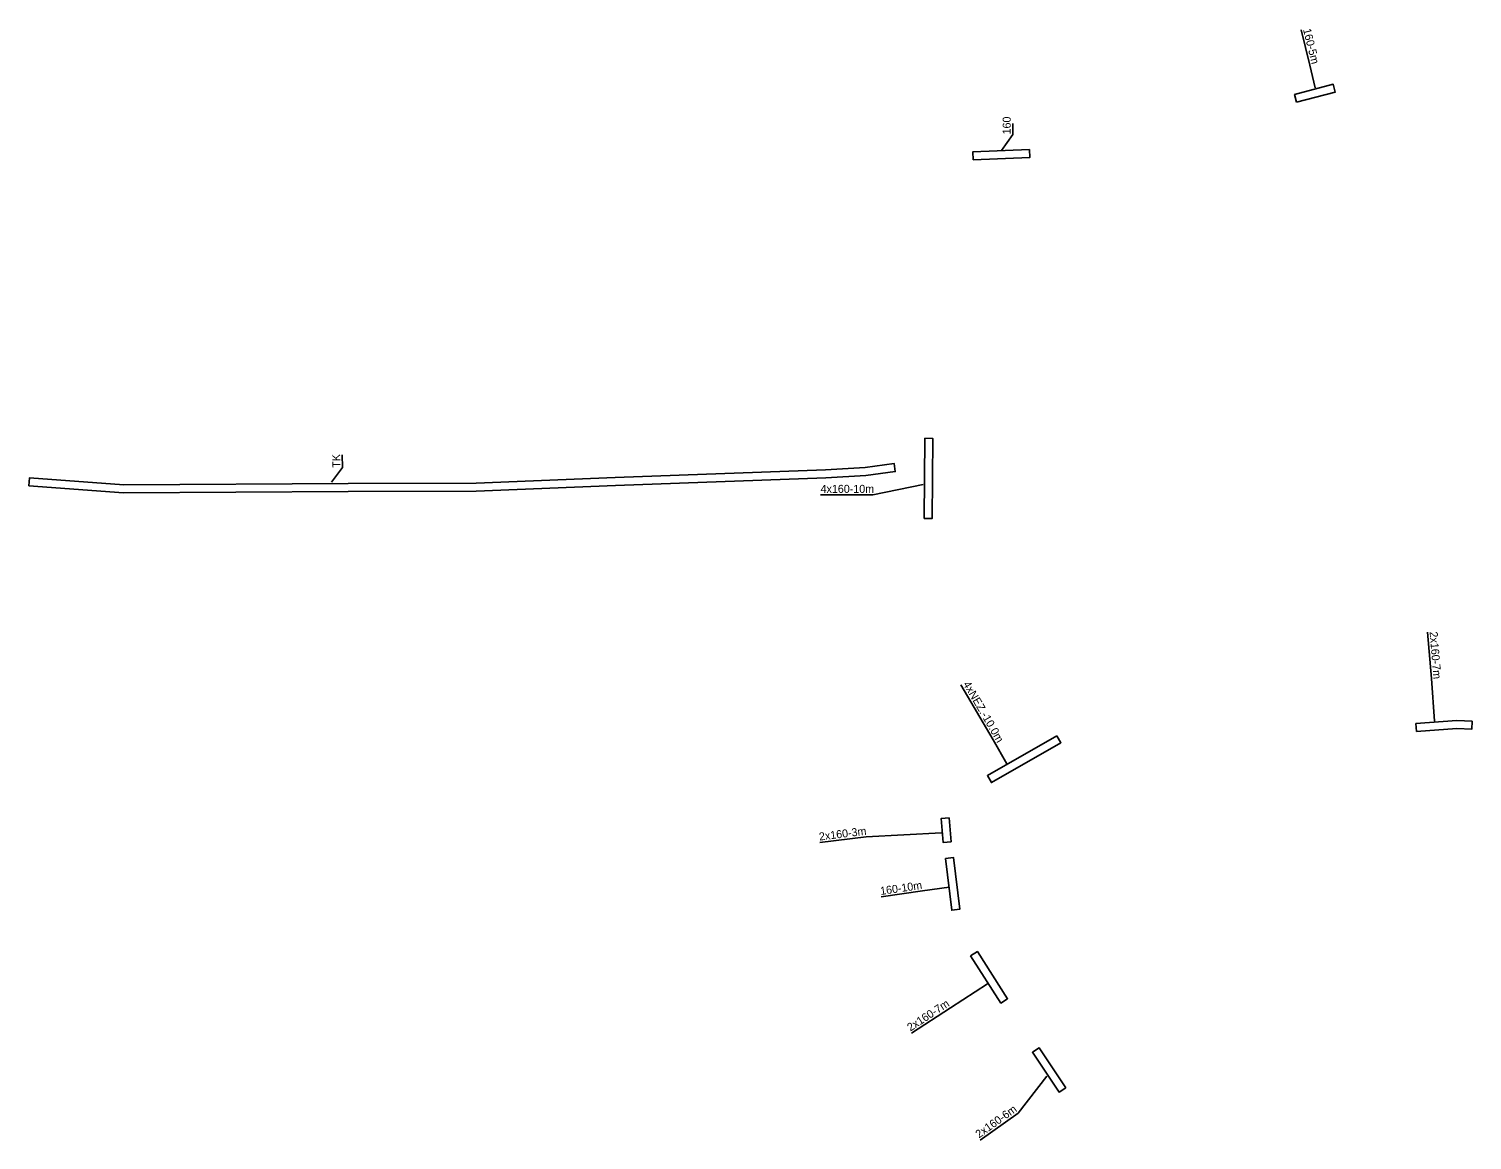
# Model space of a CAD drawing. Extents: x -732155 to -731960, y -1048709 to -1047981.
# Drawn here: x -732154.9 to -731974.6, y -1048120 to -1047981.1 of the extents above; entities that cross this region are included whole.
import ezdxf

# ---------------------------------------------------------------- set-up
doc = ezdxf.new("R2010")
doc.units = 0
doc.layers.add('Chránička', color=7, linetype='Continuous')
doc.layers.add('ST_CHRANICKA_POPIS', color=7, linetype='Continuous')

msp = doc.modelspace()

# ---------------------------------------------------------------- linework, layer by layer
at = {"layer": 'Chránička'}
for points in [[(-731996.497, -1047990.229), (-731996.749, -1047989.261), (-731991.91, -1047988.002), (-731991.658, -1047988.97), (-731996.497, -1047990.229)], [(-732036.908, -1047997.458), (-732036.952, -1047996.458), (-732029.874, -1047996.152), (-732029.83, -1047997.152), (-732036.908, -1047997.458)], [(-732042.939, -1048032.249), (-732041.939, -1048032.257), (-732042.017, -1048042.257), (-732043.017, -1048042.249), (-732042.939, -1048032.249)], [(-732154.881, -1048038.194), (-732154.809, -1048037.196), (-732143.028, -1048038.053), (-732114.98, -1048037.884), (-732099.001, -1048037.839), (-732081.607, -1048037.142), (-732055.352, -1048036.193), (-732050.398, -1048035.895), (-732046.761, -1048035.406), (-732046.627, -1048036.398), (-732050.302, -1048036.891), (-732055.304, -1048037.191), (-732081.569, -1048038.142), (-732098.979, -1048038.839), (-732114.976, -1048038.884), (-732143.062, -1048039.053), (-732154.881, -1048038.194)], [(-731981.518, -1048068.894), (-731981.59, -1048067.896), (-731976.481, -1048067.524), (-731974.557, -1048067.605), (-731974.599, -1048068.605), (-731976.465, -1048068.526), (-731981.518, -1048068.894)], [(-732026.441, -1048069.42), (-732025.943, -1048070.288), (-732034.616, -1048075.266), (-732035.114, -1048074.398), (-732026.441, -1048069.42)], [(-732039.638, -1048082.681), (-732040.634, -1048082.769), (-732040.899, -1048079.781), (-732039.903, -1048079.693), (-732039.638, -1048082.681)], [(-732040.366, -1048084.76), (-732039.374, -1048084.638), (-732038.575, -1048091.102), (-732039.567, -1048091.224), (-732040.366, -1048084.76)], [(-732037.215, -1048096.947), (-732036.373, -1048096.407), (-732032.591, -1048102.297), (-732033.433, -1048102.837), (-732037.215, -1048096.947)], [(-732025.331, -1048113.411), (-732026.163, -1048113.965), (-732029.489, -1048108.971), (-732028.657, -1048108.417), (-732025.331, -1048113.411)]]:
    msp.add_lwpolyline(points, close=True, dxfattribs=at)
at = {"layer": 'ST_CHRANICKA_POPIS'}
for points in [[(-731995.935, -1047981.209), (-731994.837, -1047985.603), (-731994.161, -1047988.449)], [(-732033.374, -1047996.282), (-732031.96, -1047994.266), (-732031.96, -1047992.892)], [(-732117.054, -1048037.719), (-732115.692, -1048035.905), (-732115.737, -1048034.328)], [(-732055.963, -1048039.313), (-732049.443, -1048039.313), (-732043.142, -1048038.007)], [(-731980.121, -1048056.463), (-731979.644, -1048062.277), (-731979.242, -1048067.591)], [(-732038.423, -1048063.073), (-732034.419, -1048069.951), (-732032.713, -1048072.951)], [(-732056.062, -1048082.778), (-732050.274, -1048082.054), (-732040.845, -1048081.568)], [(-732048.409, -1048089.575), (-732043.248, -1048088.821), (-732039.888, -1048088.365)], [(-732044.6, -1048106.615), (-732039.723, -1048103.414), (-732035.102, -1048100.422)], [(-732036.028, -1048119.967), (-732031.282, -1048116.575), (-732027.676, -1048111.96)]]:
    msp.add_lwpolyline(points, dxfattribs=at)

# ---------------------------------------------------------------- texts
for s, rotation, p in [('160-5m', 284.02877, (-731995.692, -1047981.148)), ('160', 90, (-732032.21, -1047994.266)), ('TK', 91.64097, (-732115.941, -1048035.912)), ('2x160-7m', 274.69141, (-731979.871, -1048056.443)), ('4xNEZ.-10.0m', 300.2033, (-732038.207, -1048062.947)), ('2x160-3m', 7.12875, (-732056.093, -1048082.53)), ('160-10m', 8.31117, (-732048.445, -1048089.328)), ('2x160-7m', 33.28095, (-732044.737, -1048106.406)), ('2x160-6m', 35.55195, (-732036.173, -1048119.764))]:
    msp.add_text(s, height=1, rotation=rotation, dxfattribs=at).set_placement(p)
msp.add_text('4x160-10m', height=1, dxfattribs=at).set_placement((-732055.963, -1048039.063))

doc.saveas('drawing.dxf')
